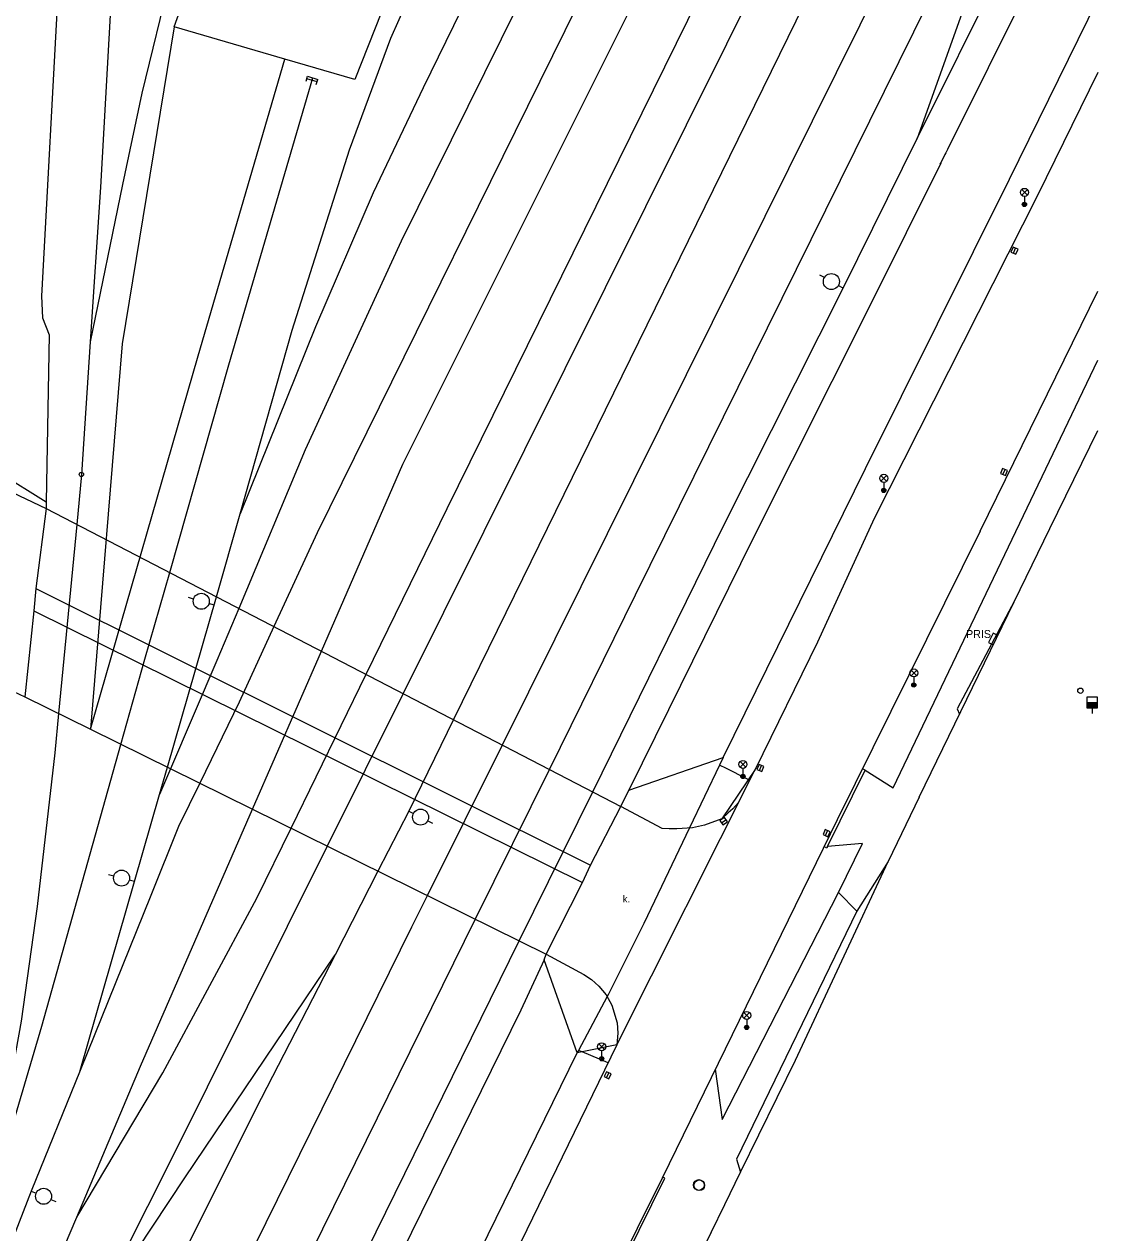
# Model space of a CAD drawing. Extents: x -598932 to -598196, y -1162207 to -1161504.
# Drawn here: x -598296.1 to -598195.6, y -1161816.9 to -1161703.7 of the extents above; entities that cross this region are included whole.
import ezdxf

# ---------------------------------------------------------------- set-up
doc = ezdxf.new("R2010")
doc.units = 0
for name, color, linetype in [('DOP - kresba z DSPS bez soueadnic', 7, 'Continuous'), ('DOP - kresba z DSPS bez souradnic - shora neviditelna', 7, 'Continuous'), ('Level 12', 7, 'Continuous'), ('Level 24', 7, 'Continuous'), ('Level 27', 7, 'Continuous'), ('Level 28', 7, 'Continuous'), ('Level 33', 7, 'Continuous'), ('specificka linie pasportu komunikaci', 7, 'Continuous'), ('TM - CD - osa koleji', 7, 'Continuous'), ('TM - chodniky - VP', 7, 'Continuous'), ('TM - komunikace - VP', 7, 'Continuous'), ('TM - letecke snimky - pomocna linie', 7, 'Continuous'), ('TM - plot dreveny_ kovovy - VP', 7, 'Continuous'), ('TM - popis objektu', 7, 'Continuous'), ('TM - popis povrchu', 7, 'Continuous'), ('TM - rozhrani ploch obecne - VP', 7, 'Continuous'), ('TM - vjezd na pozemek', 7, 'Continuous'), ('TM - zed operna - VP', 7, 'Continuous')]:
    doc.layers.add(name, color=color, linetype=linetype)

msp = doc.modelspace()

# ---------------------------------------------------------------- linework, layer by layer
at = {"layer": 'DOP - kresba z DSPS bez soueadnic'}
for points in [[(-598282.05, -1161703.94), (-598271.88, -1161675.66)], [(-598259.54, -1161694.75), (-598265.13, -1161708.88)], [(-598292.88, -1161699.67), (-598294.46, -1161729.18)], [(-598265.13, -1161708.88), (-598271.68, -1161706.97), (-598282.05, -1161703.94)], [(-598294.46, -1161729.18), (-598294.37, -1161731.21)], [(-598294.37, -1161731.21), (-598293.77, -1161732.8)], [(-598293.77, -1161732.8), (-598294.03, -1161748.44)], [(-598302.87, -1161742.97), (-598294.03, -1161748.44)], [(-598294.03, -1161748.44), (-598294.04, -1161749.08)], [(-598294.04, -1161749.08), (-598294.99, -1161756.56)], [(-598294.99, -1161756.56), (-598295.19, -1161758.67)], [(-598295.19, -1161758.67), (-598296.04, -1161766.73)]]:
    msp.add_lwpolyline(points, dxfattribs=at)
at = {"layer": 'DOP - kresba z DSPS bez souradnic - shora neviditelna'}
for points in [[(-598297.83, -1161747.26), (-598294.04, -1161749.08)], [(-598294.04, -1161749.08), (-598240.21, -1161776.98)], [(-598294.99, -1161756.56), (-598243.06, -1161782.5)], [(-598295.19, -1161758.67), (-598243.81, -1161784.1)], [(-598299.79, -1161764.96), (-598296.04, -1161766.73)], [(-598296.04, -1161766.73), (-598289.89, -1161769.76), (-598247.21, -1161790.83)]]:
    msp.add_lwpolyline(points, dxfattribs=at)
at = {"layer": 'Level 12'}
for p, q in [((-598269.7, -1161709.05), (-598269.55, -1161708.58)), ((-598268.67, -1161709.12), (-598269.62, -1161708.82)), ((-598269.55, -1161708.58), (-598268.59, -1161708.88)), ((-598268.75, -1161709.36), (-598268.59, -1161708.88)), ((-598221.16, -1161727.45), (-598221.6, -1161727.21)), ((-598219.42, -1161728.43), (-598219.86, -1161728.19)), ((-598280.23, -1161757.56), (-598280.71, -1161757.41)), ((-598278.31, -1161758.13), (-598278.79, -1161757.99)), ((-598260.09, -1161777.42), (-598259.64, -1161777.65)), ((-598258.31, -1161778.33), (-598257.86, -1161778.56)), ((-598287.7, -1161783.51), (-598288.19, -1161783.39)), ((-598285.77, -1161784.02), (-598286.25, -1161783.89)), ((-598295.43, -1161813.02), (-598294.97, -1161813.22)), ((-598293.59, -1161813.8), (-598293.13, -1161814))]:
    msp.add_line(p, q, dxfattribs=at)
for centre, radius in [((-598220.51, -1161727.82), 0.75), ((-598290.74, -1161745.89), 0.2), ((-598279.51, -1161757.77), 0.75), ((-598258.98, -1161777.99), 0.75), ((-598286.98, -1161783.7), 0.75), ((-598294.28, -1161813.51), 0.75)]:
    msp.add_circle(centre, radius, dxfattribs=at)
at = {"layer": 'Level 24'}
msp.add_lwpolyline([(-598205.36, -1161761.86), (-598204.91, -1161760.96), (-598205.36, -1161760.74), (-598205.81, -1161761.64)], close=True, dxfattribs=at)
at = {"layer": 'Level 27'}
for p, q in [((-598203.46, -1161725.15), (-598203.26, -1161724.69)), ((-598204.44, -1161745.89), (-598204.24, -1161745.43)), ((-598227.25, -1161773.62), (-598227.05, -1161773.16)), ((-598230.81, -1161778.51), (-598230.39, -1161778.23)), ((-598221.06, -1161779.72), (-598220.86, -1161779.26)), ((-598241.57, -1161802.4), (-598241.35, -1161801.94))]:
    msp.add_line(p, q, dxfattribs=at)
for points in [[(-598203.23, -1161725.25), (-598203.03, -1161724.79), (-598203.49, -1161724.59), (-598203.69, -1161725.05)], [(-598204.21, -1161745.99), (-598204.01, -1161745.53), (-598204.47, -1161745.33), (-598204.67, -1161745.79)], [(-598227.02, -1161773.72), (-598226.82, -1161773.26), (-598227.28, -1161773.06), (-598227.48, -1161773.52)], [(-598230.67, -1161778.72), (-598230.25, -1161778.44), (-598230.53, -1161778.02), (-598230.95, -1161778.3)], [(-598220.83, -1161779.82), (-598220.63, -1161779.36), (-598221.09, -1161779.16), (-598221.29, -1161779.62)], [(-598241.34, -1161802.5), (-598241.13, -1161802.05), (-598241.58, -1161801.84), (-598241.79, -1161802.29)]]:
    msp.add_lwpolyline(points, close=True, dxfattribs=at)
for centre in [(-598232.92, -1161812.45), (-598232.88, -1161812.48)]:
    msp.add_circle(centre, 0.5, dxfattribs=at)
at = {"layer": 'Level 28'}
for p, q in [((-598196.59, -1161767.24), (-598195.59, -1161767.24)), ((-598196.59, -1161767.29), (-598195.59, -1161767.29)), ((-598196.59, -1161767.34), (-598195.59, -1161767.34)), ((-598196.59, -1161767.39), (-598195.59, -1161767.39)), ((-598196.59, -1161767.44), (-598195.59, -1161767.44)), ((-598196.59, -1161767.49), (-598195.59, -1161767.49)), ((-598196.59, -1161767.54), (-598195.59, -1161767.54)), ((-598196.59, -1161767.59), (-598195.59, -1161767.59)), ((-598196.59, -1161767.64), (-598195.59, -1161767.64)), ((-598196.59, -1161767.69), (-598195.59, -1161767.69)), ((-598196.09, -1161767.74), (-598196.09, -1161768.27))]:
    msp.add_line(p, q, dxfattribs=at)
msp.add_lwpolyline([(-598196.59, -1161767.74), (-598195.59, -1161767.74), (-598195.59, -1161766.74), (-598196.59, -1161766.74)], close=True, dxfattribs=at)
msp.add_circle((-598197.19, -1161766.15), 0.25, dxfattribs=at)
at = {"layer": 'Level 33'}
for p, q in [((-598202.69, -1161719.73), (-598202.16, -1161719.2)), ((-598202.69, -1161719.2), (-598202.16, -1161719.73)), ((-598202.43, -1161719.84), (-598202.43, -1161720.59)), ((-598215.87, -1161746.52), (-598215.34, -1161745.99)), ((-598215.87, -1161745.99), (-598215.34, -1161746.52)), ((-598215.6, -1161746.63), (-598215.6, -1161747.38)), ((-598213.05, -1161764.75), (-598212.52, -1161764.22)), ((-598213.05, -1161764.22), (-598212.52, -1161764.75)), ((-598212.79, -1161764.86), (-598212.79, -1161765.61)), ((-598229.05, -1161773.31), (-598228.52, -1161772.78)), ((-598229.05, -1161772.78), (-598228.52, -1161773.31)), ((-598228.79, -1161773.42), (-598228.79, -1161774.17)), ((-598228.71, -1161796.83), (-598228.18, -1161796.3)), ((-598228.71, -1161796.3), (-598228.18, -1161796.83)), ((-598228.44, -1161796.94), (-598228.44, -1161797.69)), ((-598242.28, -1161799.76), (-598241.75, -1161799.23)), ((-598242.28, -1161799.23), (-598241.75, -1161799.76)), ((-598242.02, -1161799.87), (-598242.02, -1161800.62))]:
    msp.add_line(p, q, dxfattribs=at)
for centre, radius in [((-598202.43, -1161719.46), 0.375), ((-598202.43, -1161720.59), 0.2), ((-598202.43, -1161720.59), 0.145), ((-598202.43, -1161720.59), 0.0876), ((-598215.6, -1161746.25), 0.375), ((-598215.6, -1161747.38), 0.2), ((-598215.6, -1161747.38), 0.145), ((-598215.6, -1161747.38), 0.0876), ((-598212.79, -1161764.48), 0.375), ((-598212.79, -1161765.61), 0.2), ((-598212.79, -1161765.61), 0.145), ((-598212.79, -1161765.61), 0.0876), ((-598228.79, -1161773.05), 0.375), ((-598228.79, -1161774.17), 0.2), ((-598228.79, -1161774.17), 0.145), ((-598228.79, -1161774.17), 0.0876), ((-598228.44, -1161796.57), 0.375), ((-598228.44, -1161797.69), 0.2), ((-598228.44, -1161797.69), 0.145), ((-598228.44, -1161797.69), 0.0876), ((-598242.02, -1161799.5), 0.375), ((-598242.02, -1161800.62), 0.2), ((-598242.02, -1161800.62), 0.145), ((-598242.02, -1161800.62), 0.0876)]:
    msp.add_circle(centre, radius, dxfattribs=at)
at = {"layer": 'specificka linie pasportu komunikaci'}
for points in [[(-598217.35, -1161773.59), (-598214.72, -1161775.23), (-598195.56, -1161735.18)], [(-598203.35, -1161757.73), (-598208.73, -1161767.84), (-598208.52, -1161768.35)], [(-598230.64, -1161772.41), (-598230.98, -1161773.12), (-598233.79, -1161779), (-598238.07, -1161787.95), (-598241.13, -1161794.06), (-598241.38, -1161794.56), (-598241.51, -1161794.8), (-598244.19, -1161799.84)], [(-598228.16, -1161774.52), (-598228.29, -1161774.46), (-598230.47, -1161773.37), (-598230.85, -1161773.18), (-598230.98, -1161773.12)], [(-598220.86, -1161780.74), (-598217.35, -1161773.59)], [(-598217.35, -1161773.59), (-598217.59, -1161773.45)], [(-598229.22, -1161776.63), (-598229.49, -1161776.93), (-598229.75, -1161777.22), (-598230.17, -1161777.58), (-598230.76, -1161778.14)], [(-598220.86, -1161780.74), (-598220.93, -1161780.88), (-598221.15, -1161780.77), (-598221.19, -1161780.75)], [(-598219.84, -1161785.06), (-598217.61, -1161780.46), (-598220.86, -1161780.74)], [(-598215.2, -1161782.13), (-598218.12, -1161786.79)], [(-598230.74, -1161806.32), (-598219.84, -1161785.06)], [(-598218.12, -1161786.79), (-598219.84, -1161785.06)], [(-598218.12, -1161786.79), (-598229.4, -1161810.03), (-598229.01, -1161811.26)], [(-598244.19, -1161799.84), (-598244.31, -1161800.07)], [(-598243.85, -1161799.98), (-598244.19, -1161799.84)], [(-598241.42, -1161800.99), (-598243.85, -1161799.98)], [(-598231.38, -1161801.59), (-598230.74, -1161806.32)], [(-598239.96, -1161819.03), (-598239.72, -1161819.15), (-598236.11, -1161811.82), (-598236.33, -1161811.72)]]:
    msp.add_lwpolyline(points, dxfattribs=at)
at = {"layer": 'TM - CD - osa koleji'}
for points in [[(-598268.26, -1161762.44), (-598260.64, -1161744.93), (-598232.73, -1161689.05)], [(-598226.55, -1161697.97), (-598260.62, -1161766.4)], [(-598221.51, -1161698.61), (-598251, -1161758.85), (-598255.9, -1161768.85)], [(-598206.58, -1161697.88), (-598212.47, -1161714.42)], [(-598287.85, -1161699.5), (-598288.94, -1161718.96), (-598289.91, -1161733.46), (-598290.74, -1161745.89), (-598291.18, -1161750.56)], [(-598282.37, -1161699.03), (-598285.09, -1161710.18), (-598286.88, -1161718.73), (-598289.91, -1161733.46)], [(-598278.09, -1161757.35), (-598275.88, -1161749.58), (-598271, -1161732.38), (-598265.63, -1161715.49), (-598261.76, -1161705.01), (-598259.43, -1161699.73)], [(-598248.31, -1161698.76), (-598260.8, -1161724.04), (-598269.77, -1161743.58), (-598275.99, -1161758.43)], [(-598253.78, -1161699.48), (-598258.73, -1161709.67), (-598263.43, -1161719.5), (-598268.81, -1161732.06), (-598275.88, -1161749.58)], [(-598243.16, -1161699.61), (-598268.67, -1161751.36), (-598272.71, -1161760.14)], [(-598264.08, -1161764.61), (-598256.5, -1161749.07), (-598231.79, -1161698.94)], [(-598251.32, -1161771.22), (-598226.7, -1161721.69), (-598215.61, -1161699.28)], [(-598210.06, -1161698.86), (-598238.88, -1161757.18), (-598246.92, -1161773.5)], [(-598242.86, -1161775.61), (-598230.59, -1161750.64), (-598219.42, -1161728.43), (-598212.47, -1161714.42), (-598204.7, -1161698.78)], [(-598282.47, -1161755.07), (-598276.92, -1161735.62), (-598269.07, -1161708.73)], [(-598291.18, -1161750.56), (-598292.87, -1161768.29)], [(-598287.03, -1161771.17), (-598284.79, -1161763.19), (-598282.47, -1161755.07)], [(-598282.68, -1161773.32), (-598278.09, -1161757.35)], [(-598275.99, -1161758.43), (-598278.04, -1161763.32), (-598282.39, -1161773.46)], [(-598272.71, -1161760.14), (-598275.97, -1161767.22), (-598279.66, -1161774.81)], [(-598274.71, -1161777.25), (-598268.26, -1161762.44)], [(-598271.11, -1161779.03), (-598264.08, -1161764.61)], [(-598260.62, -1161766.4), (-598267.73, -1161780.7)], [(-598292.87, -1161768.29), (-598293.22, -1161771.98), (-598294.88, -1161786.35), (-598296.39, -1161797.1), (-598299.64, -1161815.15)], [(-598255.9, -1161768.85), (-598260.09, -1161777.42), (-598262.97, -1161783.05)], [(-598310.31, -1161852.18), (-598307.8, -1161843.38), (-598302.86, -1161826.04), (-598299.64, -1161815.15), (-598294.44, -1161797.56), (-598287.03, -1161771.17)], [(-598258.34, -1161785.34), (-598251.32, -1161771.22)], [(-598290.86, -1161801.71), (-598285.77, -1161784.02), (-598283.42, -1161775.88), (-598282.68, -1161773.32)], [(-598282.39, -1161773.46), (-598283.42, -1161775.88)], [(-598246.92, -1161773.5), (-598253.85, -1161787.55)], [(-598279.66, -1161774.81), (-598281.63, -1161778.87), (-598284.25, -1161785.34), (-598290.86, -1161801.71), (-598295.43, -1161813.02), (-598300.65, -1161826.42)], [(-598249.73, -1161789.59), (-598242.86, -1161775.61)], [(-598315.27, -1161885.28), (-598312.12, -1161874.12), (-598307.82, -1161858.87), (-598302.71, -1161843.47), (-598298.71, -1161833.11), (-598295.68, -1161826.12), (-598291.17, -1161815.46), (-598285.2, -1161801.33), (-598274.71, -1161777.25)], [(-598291.17, -1161815.46), (-598283.11, -1161801.95), (-598274.3, -1161785.57), (-598271.11, -1161779.03)], [(-598267.73, -1161780.7), (-598282.72, -1161810.8), (-598290.04, -1161825.36), (-598295.14, -1161835.51), (-598301.33, -1161848.65), (-598306.3, -1161859.78)], [(-598262.97, -1161783.05), (-598266.99, -1161790.88), (-598273.89, -1161804.34), (-598292.91, -1161842.33)], [(-598330.7, -1161957.12), (-598323.25, -1161930.13), (-598318.14, -1161914.72), (-598309.03, -1161890.52), (-598298.97, -1161868.44), (-598286, -1161841.52), (-598259.79, -1161788.26), (-598258.34, -1161785.34)], [(-598253.85, -1161787.55), (-598277.35, -1161835.24), (-598288.92, -1161858.05), (-598298.17, -1161877.98), (-598306.86, -1161898.82), (-598315.14, -1161920.44), (-598321.21, -1161940.59), (-598327.42, -1161961.55), (-598336.66, -1161994.53)], [(-598332.49, -1161997.92), (-598324.93, -1161971.61), (-598314.3, -1161934.07), (-598308.24, -1161914.84), (-598301.06, -1161896.46), (-598291.55, -1161875.15), (-598278.3, -1161847.71), (-598249.73, -1161789.59)], [(-598290.04, -1161825.36), (-598281.04, -1161811.79), (-598266.99, -1161790.88)]]:
    msp.add_lwpolyline(points, dxfattribs=at)
at = {"layer": 'TM - chodniky - VP'}
msp.add_lwpolyline([(-598240.61, -1161799.32), (-598244.31, -1161800.07)], dxfattribs=at)
at = {"layer": 'TM - komunikace - VP'}
for points in [[(-598195.56, -1161708.24), (-598201.21, -1161719.75), (-598216.5, -1161750)], [(-598206.57, -1161751.2), (-598195.56, -1161728.72)], [(-598216.5, -1161750), (-598221.81, -1161761.59), (-598227.66, -1161773.52)], [(-598206.57, -1161751.2), (-598219.96, -1161778.23), (-598236.37, -1161811.8)], [(-598227.66, -1161773.52), (-598230.76, -1161778.14)], [(-598236.36, -1161779.04), (-598240.21, -1161776.98)], [(-598234.99, -1161779.1), (-598235.69, -1161779.1), (-598236.36, -1161779.04)], [(-598230.76, -1161778.14), (-598232.39, -1161778.74), (-598233.5, -1161778.98), (-598234.99, -1161779.1)], [(-598247.21, -1161790.83), (-598243.68, -1161792.72)], [(-598243.68, -1161792.72), (-598242.96, -1161793.19), (-598242.28, -1161793.82), (-598241.6, -1161794.64), (-598241.08, -1161795.59), (-598240.56, -1161797.27), (-598240.52, -1161798.24), (-598240.61, -1161799.32)], [(-598240.61, -1161799.32), (-598244.6, -1161807.54), (-598263.48, -1161846.38)], [(-598236.37, -1161811.8), (-598245.76, -1161830.72)]]:
    msp.add_lwpolyline(points, dxfattribs=at)
at = {"layer": 'TM - letecke snimky - pomocna linie'}
for points in [[(-598195.56, -1161686.88), (-598202.01, -1161700.1), (-598209.64, -1161715.44), (-598209.79, -1161715.75), (-598209.87, -1161715.92), (-598210.31, -1161716.82), (-598210.27, -1161716.72), (-598216.74, -1161729.77), (-598227.9, -1161751.97), (-598235.75, -1161767.94), (-598239.48, -1161775.47)], [(-598282.05, -1161703.94), (-598286.91, -1161733.66), (-598289.89, -1161769.76)], [(-598289.89, -1161769.76), (-598279.8, -1161734.79), (-598271.68, -1161706.97)], [(-598247.39, -1161791.37), (-598249.58, -1161796.08), (-598275.61, -1161849.03), (-598288.83, -1161876.41), (-598298.29, -1161897.62), (-598305.41, -1161915.84), (-598311.43, -1161934.93), (-598312.26, -1161937.86), (-598312.21, -1161937.71), (-598322.05, -1161972.43), (-598326.74, -1161988.76), (-598328.41, -1161995.16)]]:
    msp.add_lwpolyline(points, dxfattribs=at)
at = {"layer": 'TM - plot dreveny_ kovovy - VP'}
for points in [[(-598200.05, -1161750.95), (-598195.56, -1161741.78)], [(-598212.3, -1161776.13), (-598200.05, -1161750.95)], [(-598223.88, -1161800.75), (-598215.2, -1161782.13)], [(-598231.76, -1161816.89), (-598230.48, -1161814.27), (-598229.01, -1161811.26), (-598223.88, -1161800.75)]]:
    msp.add_lwpolyline(points, dxfattribs=at)
at = {"layer": 'TM - rozhrani ploch obecne - VP'}
msp.add_lwpolyline([(-598240.61, -1161799.32), (-598227.66, -1161773.52)], dxfattribs=at)
at = {"layer": 'TM - vjezd na pozemek'}
for points in [[(-598212.3, -1161776.13), (-598215.2, -1161782.13)], [(-598243.06, -1161782.5), (-598240.21, -1161776.98)], [(-598247.21, -1161790.83), (-598243.81, -1161784.1)], [(-598231.76, -1161816.89), (-598234.14, -1161821.62)]]:
    msp.add_lwpolyline(points, dxfattribs=at)
at = {"layer": 'TM - zed operna - VP'}
for points in [[(-598240.21, -1161776.98), (-598239.48, -1161775.47), (-598230.64, -1161772.41), (-598217.3, -1161745.33), (-598203.83, -1161718.22), (-598195.56, -1161701.37)], [(-598243.81, -1161784.1), (-598243.06, -1161782.5)], [(-598244.31, -1161800.07), (-598247.39, -1161791.37), (-598247.21, -1161790.83)], [(-598266.32, -1161845), (-598244.31, -1161800.07)]]:
    msp.add_lwpolyline(points, dxfattribs=at)

# ---------------------------------------------------------------- texts
at = {"layer": 'TM - popis objektu'}
msp.add_text('PRIS', height=0.75, dxfattribs=at).set_placement((-598207.9, -1161761.21))
at = {"layer": 'TM - popis povrchu'}
msp.add_text('k.', height=0.65, dxfattribs=at).set_placement((-598240.04, -1161785.98))

doc.saveas('drawing.dxf')
